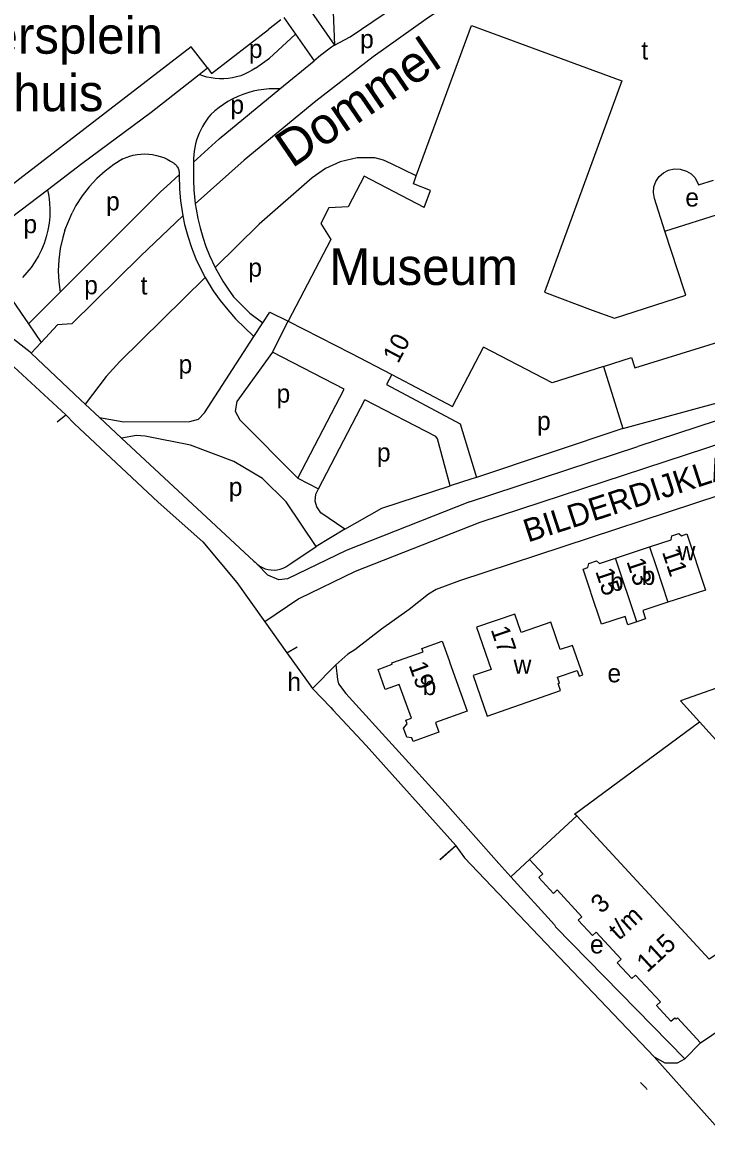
# Model space of a CAD drawing. Extents: x 160673 to 161924, y 382258 to 384145.
# Drawn here: x 161504.7 to 161653.4, y 382644.7 to 382888.8 of the extents above; entities that cross this region are included whole.
import ezdxf

# ---------------------------------------------------------------- set-up
doc = ezdxf.new("R2010")
doc.units = 0
for name, color, linetype in [('BLT_Basislijn', 7, 'Continuous'), ('BLT_Bebouwing', 7, 'Continuous'), ('BLT_Bebouwing_beschrifting', 7, 'Continuous'), ('BLT_Centroide', 7, 'Continuous'), ('BLT_Huisnummer', 7, 'Continuous'), ('BLT_Huisnummer_ tussenligend', 7, 'Continuous'), ('BLT_Huisnummer_reeks', 7, 'Continuous'), ('BLT_Onderverdeling_panden', 7, 'Continuous'), ('BLT_Straatnaam', 7, 'Continuous'), ('BLT_Vlakafsluiter', 7, 'Continuous'), ('BLT_Waternaam_spoorwegen', 7, 'Continuous')]:
    doc.layers.add(name, color=color, linetype=linetype)

msp = doc.modelspace()

# ---------------------------------------------------------------- linework, layer by layer
at = {"layer": 'BLT_Basislijn'}
for p, q in [((161566.37, 382892.67), (161572.53, 382883.88)), ((161572.2, 382891.02), (161572.53, 382883.88)), ((161561.52, 382889.86), (161564.04, 382886.25)), ((161561.1, 382883.53), (161564.04, 382886.25)), ((161564.04, 382886.25), (161568.06, 382880.47)), ((161558.4, 382881.03), (161561.1, 382883.53)), ((161555.33, 382878.86), (161558.4, 382881.03)), ((161536.04, 382853.17), (161538.77, 382855.63)), ((161513.89, 382843.57), (161515.48, 382847.41)), ((161521.16, 382838.41), (161512.86, 382830.1)), ((161500.79, 382830.87), (161506, 382823.23)), ((161506, 382823.23), (161508.75, 382819.2)), ((161506.37, 382817.06), (161506.59, 382816.86)), ((161506.59, 382816.86), (161517.3, 382806.69)), ((161517.3, 382806.69), (161518.27, 382805.78)), ((161518.27, 382805.78), (161521.41, 382802.86)), ((161569.03, 382787.37), (161579.07, 382806.68)), ((161521.41, 382802.86), (161526.22, 382798.39)), ((161599.84, 382801.5), (161603.38, 382789.83)), ((161635.19, 382800.49), (161603.38, 382789.83)), ((161526.22, 382798.39), (161554.98, 382771.62)), ((161633.4, 382794.85), (161638.43, 382796.53)), ((161601.83, 382784.48), (161633.4, 382794.85)), ((161564.53, 382789.63), (161569.03, 382787.37)), ((161602.35, 382789.49), (161597.63, 382787.97)), ((161603.38, 382789.83), (161602.35, 382789.49)), ((161574.76, 382778.55), (161568.51, 382774.78)), ((161563, 382771.09), (161568.51, 382774.78)), ((161562.34, 382770.67), (161563, 382771.09)), ((161562.15, 382751.7), (161564.36, 382752.99)), ((161647.7, 382741.2), (161651.83, 382736.65)), ((161651.83, 382736.65), (161660.76, 382726.8)), ((161608.23, 382705.86), (161610.86, 382702.96)), ((161614.91, 382706.7), (161610.86, 382702.96)), ((161648.64, 382663.39), (161652.08, 382666.86))]:
    msp.add_line(p, q, dxfattribs=at)
for points in [[(161613.51, 382899.59), (161598.5, 382893.6), (161592.45, 382889.51), (161580.89, 382881.32), (161568.45, 382871.7), (161552.84, 382858.82), (161542.24, 382849.33)], [(161572.53, 382883.88), (161575.89, 382885.63), (161583.3, 382890.69), (161591.95, 382895.26), (161613.51, 382899.59)], [(161572.53, 382883.88), (161571.85, 382883.4), (161569.49, 382881.61), (161568.06, 382880.47)], [(161560.63, 382874.35), (161568.06, 382880.47)], [(161543.06, 382877.47), (161544.88, 382878.89)], [(161555.33, 382878.86), (161554.59, 382878.38), (161553.8, 382877.94), (161552.97, 382877.55), (161552.11, 382877.21), (161551.22, 382876.94), (161550.3, 382876.74), (161549.38, 382876.6), (161548.44, 382876.52), (161547.5, 382876.52), (161546.57, 382876.58), (161545.66, 382876.71), (161544.76, 382876.91), (161543.9, 382877.16), (161543.06, 382877.47)], [(161510.14, 382852.4), (161517.61, 382858.08), (161532.63, 382869.26), (161543.06, 382877.47)], [(161541.84, 382858.41), (161547.43, 382863.48), (161560.63, 382874.35)], [(161560.63, 382874.35), (161559.48, 382874.37), (161558.32, 382874.34), (161557.16, 382874.23), (161555.99, 382874.06), (161554.83, 382873.81), (161553.69, 382873.5), (161552.56, 382873.12), (161551.46, 382872.67), (161550.38, 382872.16), (161549.35, 382871.59), (161548.35, 382870.97), (161547.4, 382870.29), (161546.49, 382869.56), (161545.64, 382868.79)], [(161545.64, 382868.79), (161545.13, 382868.18), (161544.66, 382867.54), (161544.21, 382866.87), (161543.79, 382866.18), (161543.42, 382865.46), (161543.08, 382864.72), (161542.78, 382863.96), (161542.52, 382863.18), (161542.31, 382862.4), (161542.13, 382861.6), (161542, 382860.8), (161541.92, 382860), (161541.88, 382859.21), (161541.84, 382858.41)], [(161526.48, 382859.1), (161524.53, 382857.86), (161522.64, 382856.43), (161520.84, 382854.81), (161519.17, 382853.02), (161517.65, 382851.06), (161516.29, 382848.96), (161515.48, 382847.41)], [(161526.48, 382859.1), (161527.21, 382859.42), (161527.98, 382859.69), (161528.77, 382859.9), (161529.59, 382860.06), (161530.42, 382860.15), (161531.27, 382860.18), (161532.11, 382860.15), (161532.96, 382860.05), (161533.78, 382859.88), (161534.59, 382859.66), (161535.38, 382859.38), (161536.13, 382859.04), (161536.84, 382858.65), (161537.51, 382858.22)], [(161590.28, 382855.4), (161584.91, 382858.05), (161583.13, 382858.84), (161581.25, 382859.33), (161577.45, 382859.35), (161573.74, 382858.49), (161570.52, 382857.02), (161567.67, 382855), (161556.16, 382844.93), (161546.58, 382835.5)], [(161537.51, 382858.22), (161537.68, 382858.1), (161537.84, 382857.96), (161537.99, 382857.81), (161538.13, 382857.65), (161538.26, 382857.47), (161538.38, 382857.29), (161538.49, 382857.1), (161538.57, 382856.89), (161538.65, 382856.69), (161538.7, 382856.48), (161538.74, 382856.26), (161538.77, 382856.05), (161538.77, 382855.63)], [(161541.84, 382858.41), (161541.82, 382854.45), (161541.92, 382852.37), (161542.24, 382849.33)], [(161644.34, 382843.41), (161642.05, 382850.53), (161641.85, 382851.77), (161641.96, 382853.02), (161642.37, 382854.21), (161643.08, 382855.25), (161644.05, 382856.05), (161645.15, 382856.66), (161646.38, 382856.92), (161647.64, 382856.88), (161649.02, 382856.46), (161650.05, 382855.84), (161650.9, 382854.98), (161651.64, 382853.46), (161654.88, 382854.49)], [(161538.77, 382855.63), (161538.84, 382852.53), (161539.04, 382849.97), (161539.5, 382846.7)], [(161497.77, 382842.83), (161502.26, 382846.4), (161510.14, 382852.4)], [(161510.14, 382852.4), (161510.4, 382850.99), (161510.57, 382849.55), (161510.63, 382848.08), (161510.59, 382846.6), (161510.45, 382845.11), (161510.19, 382843.63), (161509.83, 382842.16), (161509.36, 382840.73), (161508.79, 382839.34), (161508.13, 382838), (161507.37, 382836.72), (161506.54, 382835.51), (161505.63, 382834.37), (161504.67, 382833.32)], [(161521.16, 382838.41), (161534.68, 382851.93), (161536.04, 382853.17)], [(161542.24, 382849.33), (161542.4, 382848.21), (161542.79, 382846.14), (161543.29, 382844.08), (161543.88, 382842.05), (161544.57, 382840.06), (161545.35, 382838.09), (161546.58, 382835.5)], [(161539.5, 382846.7), (161530.36, 382837.94), (161515.38, 382823.25), (161512.26, 382823.03), (161510.54, 382821.14), (161508.75, 382819.2)], [(161539.5, 382846.7), (161539.92, 382844.84), (161540.59, 382842.3), (161541.42, 382839.8), (161542.39, 382837.34), (161543.51, 382834.95), (161544.39, 382833.34)], [(161513.89, 382843.57), (161513.41, 382842.03), (161512.87, 382839.61), (161512.56, 382837.17), (161512.46, 382834.76), (161512.56, 382832.39), (161512.86, 382830.1)], [(161506.37, 382817.06), (161492.82, 382827.6), (161483.84, 382836.59)], [(161546.58, 382835.5), (161548.24, 382832.5), (161549.37, 382830.76), (161550.57, 382829.08)], [(161544.39, 382833.34), (161525.82, 382815.04), (161522.89, 382811.76), (161518.27, 382805.78)], [(161544.39, 382833.34), (161546.16, 382830.41), (161547.67, 382828.28), (161549.29, 382826.26), (161551.02, 382824.35), (161554.99, 382820.45)], [(161506, 382823.23), (161512.86, 382830.1)], [(161550.57, 382829.08), (161554.13, 382825.54), (161556.94, 382823.45)], [(161556.94, 382823.45), (161558.47, 382825.8), (161562.44, 382823.78)], [(161554.99, 382820.45), (161556.94, 382823.45)], [(161559, 382817.1), (161562.44, 382823.78)], [(161521.41, 382802.86), (161526.74, 382801.95), (161541.06, 382801.97), (161542.91, 382802.48), (161544.21, 382803.9), (161554.99, 382820.45)], [(161706.56, 382820.15), (161707.11, 382813.82), (161604.11, 382780.01)], [(161497.57, 382818.87), (161501.83, 382814.76), (161514.12, 382803.42)], [(161508.75, 382819.2), (161506.59, 382816.86)], [(161559, 382817.1), (161551.27, 382806.32), (161550.89, 382804.23), (161551.93, 382802.37), (161564.53, 382789.63)], [(161564.53, 382789.63), (161574.61, 382809.01), (161559, 382817.1)], [(161690.9, 382815.57), (161690, 382813.46), (161638.43, 382796.53)], [(161584.94, 382812.2), (161583.81, 382810.03), (161599.84, 382801.5)], [(161597.63, 382787.97), (161594.88, 382798.25), (161594.54, 382798.74), (161579.07, 382806.68)], [(161514.12, 382803.42), (161515.91, 382801.53), (161534.19, 382784.43), (161543.91, 382775.81), (161551.27, 382766.97), (161557.39, 382758.38)], [(161568.51, 382774.78), (161562, 382784.49), (161556.87, 382789.61), (161550.62, 382793.3), (161541.21, 382796.83), (161531.36, 382798.8), (161529.46, 382798.92), (161526.22, 382798.39)], [(161673.24, 382791.58), (161599.67, 382767.3), (161594.58, 382765.48), (161592.95, 382764.43), (161588.72, 382761.07), (161582.73, 382756.8), (161576.92, 382752.34), (161575.39, 382751.38), (161572.83, 382749.04)], [(161574.76, 382778.55), (161582.82, 382783.17), (161597.63, 382787.97)], [(161574.76, 382778.55), (161569.55, 382782.13), (161568.67, 382783.42), (161568.3, 382784.65), (161568.44, 382786.17), (161569.03, 382787.37)], [(161601.83, 382784.48), (161575.02, 382773.92), (161562.27, 382767.77), (161560.38, 382767.57), (161558.02, 382768.55), (161555.72, 382770.92)], [(161604.11, 382780.01), (161577.03, 382769.34), (161564.78, 382763.43), (161557.39, 382758.38)], [(161554.98, 382771.62), (161555.24, 382771.37), (161555.72, 382770.92)], [(161555.72, 382770.92), (161556.25, 382770.53), (161556.83, 382770.21), (161557.44, 382769.96), (161558.08, 382769.79), (161558.73, 382769.69), (161559.39, 382769.68), (161560.05, 382769.74), (161560.69, 382769.88), (161561.32, 382770.1), (161561.91, 382770.4), (161562.34, 382770.67)], [(161705.29, 382765.14), (161671.57, 382753.82), (161672.26, 382751.88), (161666.99, 382750.02), (161666.19, 382749.74), (161666.83, 382747.94), (161647.7, 382741.2)], [(161567.7, 382743.91), (161572.83, 382749.04)], [(161572.83, 382749.04), (161573.19, 382745.89), (161573.41, 382744.94), (161575, 382742.8), (161596.6, 382719.03), (161608.23, 382705.86)], [(161567.7, 382743.91), (161571.73, 382739.79), (161572.13, 382739.3), (161579.36, 382731.52), (161598.87, 382709.73)], [(161625.22, 382716.23), (161624.71, 382716.59), (161651.83, 382736.65)], [(161598.87, 382709.73), (161598.9, 382709.69)], [(161598.9, 382709.69), (161600.8, 382707.05), (161642.04, 382663.81)], [(161610.86, 382702.96), (161620.32, 382692.53), (161620.54, 382692.05), (161648.64, 382663.39)], [(161642.04, 382663.81), (161644.36, 382662.5), (161647.08, 382662.46), (161648.64, 382663.39)], [(161639.05, 382658.22), (161640.28, 382656.97), (161640.41, 382656.7)]]:
    msp.add_lwpolyline(points, dxfattribs=at)
at = {"layer": 'BLT_Bebouwing'}
for p, q in [((161545.8, 382877.7), (161558.19, 382887.28)), ((161544.88, 382878.89), (161545.8, 382877.7)), ((161592.03, 382848.57), (161578.94, 382855.38)), ((161589.65, 382853.69), (161590.28, 382855.4)), ((161635.19, 382800.49), (161688.4, 382814.89)), ((161584.94, 382812.2), (161598.15, 382805.24)), ((161630.96, 382813.95), (161635.19, 382800.49)), ((161633.6, 382772.24), (161641, 382774.7)), ((161625.22, 382716.23), (161614.91, 382706.7))]:
    msp.add_line(p, q, dxfattribs=at)
for points in [[(161544.88, 382878.89), (161541.31, 382883.51), (161504.06, 382854.75), (161495.3, 382847.99), (161465.24, 382886.91), (161469.19, 382889.99), (161468.67, 382890.65), (161480.42, 382899.71), (161480.96, 382899.05), (161504.44, 382917.17)], [(161560.86, 382889.34), (161558.19, 382887.28)], [(161590.28, 382855.4), (161602.29, 382888.1), (161635.01, 382876.08)], [(161635.01, 382876.08), (161618.18, 382830.12), (161628.56, 382826.24)], [(161578.94, 382855.38), (161575.45, 382848.69), (161571.27, 382848.44), (161569.53, 382845.06), (161571.72, 382841.55), (161562.44, 382823.78)], [(161592.03, 382848.57), (161593.4, 382852.25), (161589.65, 382853.69)], [(161644.34, 382843.41), (161657.17, 382847.46)], [(161648.51, 382830.59), (161644.34, 382843.41)], [(161628.56, 382826.24), (161633.37, 382824.44), (161648.88, 382829.47), (161648.51, 382830.59)], [(161562.44, 382823.78), (161576.07, 382816.84), (161584.94, 382812.2)], [(161598.15, 382805.24), (161604.92, 382818.18)], [(161630.96, 382813.95), (161619.85, 382810.37), (161604.92, 382818.18)], [(161641, 382774.7), (161645.7, 382776.26), (161645.88, 382777.14), (161647.4, 382777.65), (161647.97, 382777.14), (161649.14, 382777.53), (161653.2, 382765.3), (161644.99, 382762.71)], [(161641, 382774.7), (161642.5, 382770.2), (161644.99, 382762.71)], [(161638.21, 382758.4), (161636.28, 382757.76), (161635.67, 382759.59), (161630.57, 382757.89), (161628.34, 382764.56), (161628.24, 382764.88), (161626.57, 382769.88), (161627.59, 382770.22), (161627.77, 382771.13), (161629.47, 382771.7), (161630.15, 382771.09), (161633.6, 382772.24)], [(161644.99, 382762.71), (161639.52, 382760.89), (161640.13, 382759.04), (161638.21, 382758.4)], [(161597.43, 382749.97), (161597.59, 382749.51), (161601.38, 382738.96), (161594.45, 382736.48), (161595.21, 382734.38), (161589.6, 382732.36), (161589.31, 382733.15), (161588.23, 382733.34), (161587.53, 382735.3), (161588.32, 382736.22), (161588.03, 382737.02), (161589.22, 382737.45), (161586.58, 382744.81), (161583.53, 382743.71), (161581.97, 382748.07), (161585.07, 382749.18), (161584.97, 382749.47), (161586.45, 382750), (161591.78, 382751.92), (161591.52, 382752.64), (161595.9, 382754.21), (161597.43, 382749.97)], [(161698.1, 382697.59), (161690.32, 382709.27), (161653.96, 382685.03), (161625.22, 382716.23)], [(161614.91, 382706.7), (161617.8, 382703.57), (161616.95, 382702.78), (161620.11, 382699.35), (161620.91, 382700.09), (161626.31, 382694.25), (161625.52, 382693.52), (161628.63, 382690.16), (161629.42, 382690.89), (161634.85, 382685.01), (161633.99, 382684.21), (161637.13, 382680.8), (161637.96, 382681.57), (161643.35, 382675.75), (161642.48, 382674.94), (161645.64, 382671.52), (161646.49, 382672.3), (161646.81, 382671.96), (161647.11, 382672.24), (161652.08, 382666.86)], [(161652.08, 382666.86), (161659.5, 382671.81), (161659.05, 382672.49), (161662.52, 382674.81), (161662.96, 382674.14), (161669.99, 382678.83), (161669.57, 382679.45), (161673.08, 382681.79), (161673.49, 382681.18), (161680.47, 382685.83), (161680.01, 382686.53), (161683.46, 382688.83), (161683.89, 382688.2), (161690.94, 382692.9), (161690.51, 382693.53), (161693.96, 382695.83), (161694.43, 382695.14), (161698.1, 382697.59)]]:
    msp.add_lwpolyline(points, dxfattribs=at)
msp.add_lwpolyline([(161611.75, 382760.1), (161603.4, 382757.24), (161606.55, 382748.04), (161602.67, 382746.71), (161605.68, 382737.88), (161621.67, 382743.46), (161621.13, 382744.99), (161621.44, 382745.1), (161621.01, 382746.34), (161625.3, 382747.84), (161625.73, 382746.59), (161626.49, 382746.86), (161624.25, 382753.28), (161621.59, 382752.37), (161619.56, 382758.32), (161613.11, 382756.12)], close=True, dxfattribs=at)
at = {"layer": 'BLT_Onderverdeling_panden'}
msp.add_line((161638.21, 382758.4), (161633.6, 382772.24), dxfattribs=at)
msp.add_lwpolyline([(161630.96, 382813.95), (161637.06, 382815.91), (161637.84, 382813.63), (161680.18, 382826.76)], dxfattribs=at)
at = {"layer": 'BLT_Vlakafsluiter'}
for p, q in [((161512.18, 382801.95), (161514.12, 382803.42)), ((161557.39, 382758.38), (161562.15, 382751.7)), ((161562.15, 382751.7), (161567.7, 382743.91)), ((161595.44, 382706.71), (161598.87, 382709.73)), ((161595.47, 382706.67), (161598.9, 382709.69)), ((161642.04, 382663.81), (161659, 382644.71))]:
    msp.add_line(p, q, dxfattribs=at)

# ---------------------------------------------------------------- texts
at = {"layer": 'BLT_Bebouwing_beschrifting'}
for s, rotation, p in [('Inwonersplein', 0.0003, (161469.19, 382881.99)), ('Stadhuis', 0.0003, (161480.64, 382869.49)), ('Museum', 359.9995, (161571.36, 382831.68))]:
    msp.add_text(s, height=8, rotation=rotation, dxfattribs=at).set_placement(p)
at = {"layer": 'BLT_Centroide'}
for s, p in [('p', (161578.08, 382883.2)), ('p', (161553.89, 382881.06)), ('t', (161639.23, 382880.73)), ('p', (161549.88, 382868.94)), ('e', (161648.78, 382848.74)), ('p', (161522.85, 382847.91)), ('p', (161504.88, 382842.94)), ('p', (161553.77, 382833.49)), ('p', (161518.09, 382829.66)), ('t', (161530.34, 382829.61)), ('p', (161538.6, 382812.45)), ('p', (161559.91, 382806.09)), ('p', (161616.54, 382800.13)), ('p', (161581.73, 382793.28)), ('p', (161549.52, 382785.78)), ('w', (161647.11, 382771.81)), ('b', (161639.3, 382766.44)), ('b', (161632.39, 382765.17)), ('w', (161611.45, 382747.11)), ('h', (161562.25, 382743.36)), ('b', (161591.67, 382742.48)), ('e', (161631.85, 382745.25)), ('e', (161628.06, 382686.28))]:
    msp.add_text(s, height=4, dxfattribs=at).set_placement(p)
at = {"layer": 'BLT_Huisnummer'}
for s, rotation, p in [('11', 288.4121, (161643.68, 382773.61)), ('15', 288.435, (161629.17, 382769.41)), ('17', 288.8698, (161606.43, 382756.74)), ('19', 289.7628, (161588.58, 382749))]:
    msp.add_text(s, height=4, rotation=rotation, dxfattribs=at).set_placement(p)
at = {"layer": 'BLT_Huisnummer_ tussenligend'}
msp.add_text('13', height=4, rotation=288.4188, dxfattribs=at).set_placement((161635.94, 382771.57))
at = {"layer": 'BLT_Huisnummer_reeks'}
for s, rotation, p in [('10', 62.3967, (161586.34, 382814.44)), ('3', 42.7329, (161630.51, 382694.78)), ('t/m', 42.7329, (161634.35, 382688.98)), ('115', 42.7329, (161640.48, 382681.94))]:
    msp.add_text(s, height=4, rotation=rotation, dxfattribs=at).set_placement(p)
at = {"layer": 'BLT_Straatnaam'}
msp.add_text('BILDERDIJKLAAN', height=5, rotation=17.9765, dxfattribs=at).set_placement((161614.57, 382775.65))
at = {"layer": 'BLT_Waternaam_spoorwegen'}
msp.add_text('Dommel', height=8, rotation=34.2296, dxfattribs=at).set_placement((161563.26, 382856.96))

doc.saveas('drawing.dxf')
